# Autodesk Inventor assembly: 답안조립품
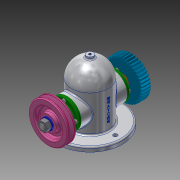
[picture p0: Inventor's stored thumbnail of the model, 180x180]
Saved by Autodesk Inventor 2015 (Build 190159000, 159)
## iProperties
Created: 2019-11
Part Number: 답안조립품
Document SubType Name: Assembly
Designer: Lineart
Author: Lineart
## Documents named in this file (14)
- C:\Users\Lineart\Desktop\491104V1027\답안조립품.iam
- C:\Users\Lineart\Desktop\491104V1027\본체.ipt
- C:\Users\Lineart\Desktop\491104V1027\V-벨트풀리.ipt
- V-벨트풀리.ipt
- C:\Users\Lineart\Desktop\491104V1027\너트 M12x1.25.ipt
- C:\Users\Lineart\Desktop\491104V1027\베어링 6203.ipt
- C:\Users\Lineart\Desktop\491104V1027\볼트 M4.ipt
- C:\Users\Lineart\Desktop\491104V1027\부시.ipt
- C:\Users\Lineart\Desktop\491104V1027\스퍼기어.ipt
- C:\Users\Lineart\Desktop\491104V1027\오일 실 26 38 8.ipt
- C:\Users\Lineart\Desktop\491104V1027\와셔 12x24.ipt
- C:\Users\Lineart\Desktop\491104V1027\축.ipt
- C:\Users\Lineart\Desktop\491104V1027\커버.ipt
- C:\Users\Lineart\Desktop\491104V1027\키 5x5x12.ipt
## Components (1 placed, 1 different names)
1. V-벨트풀리:1
